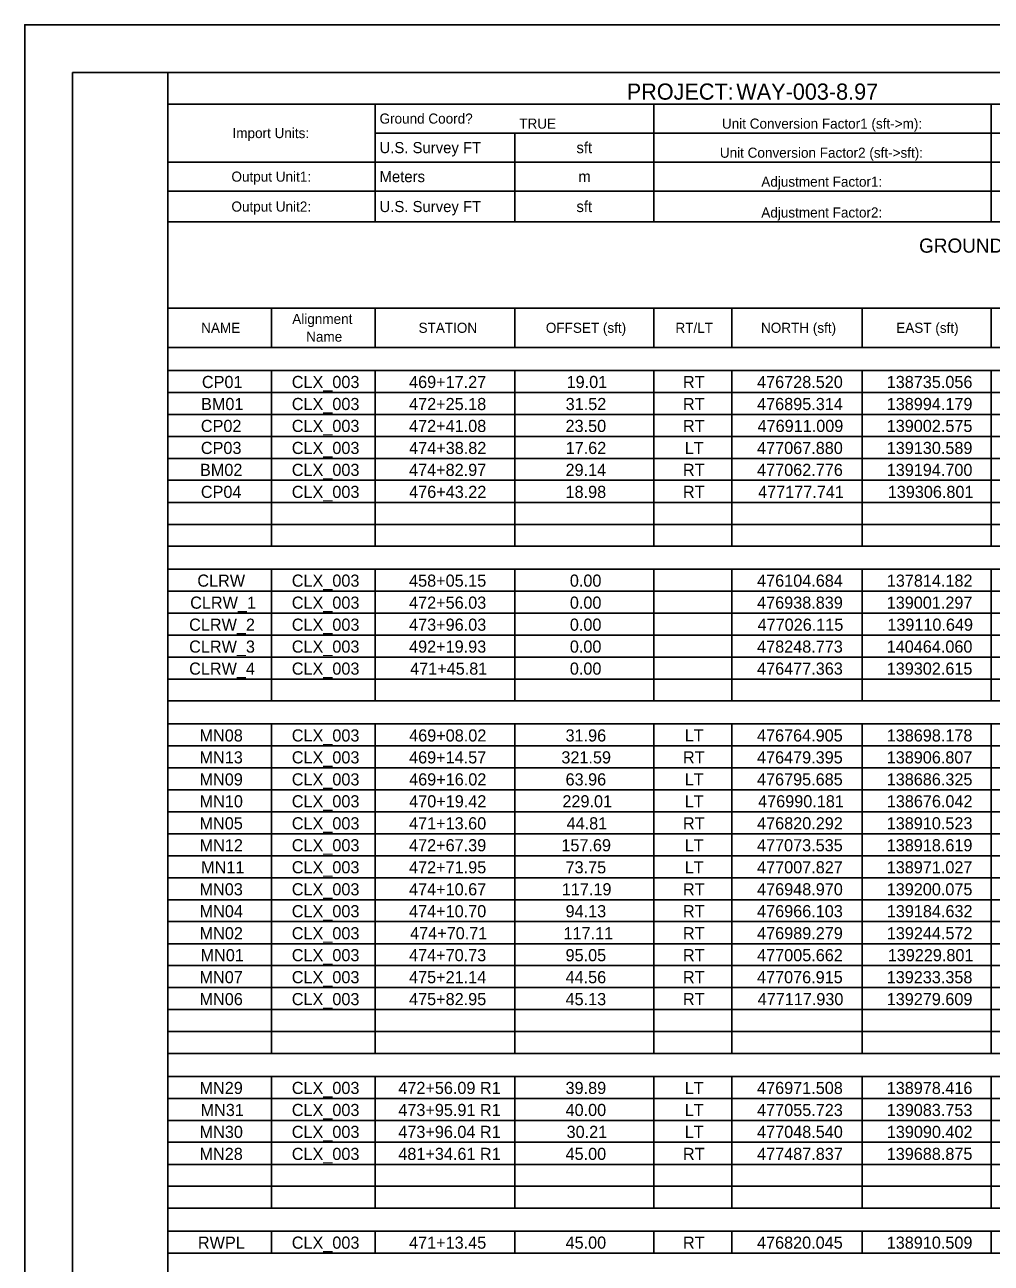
# Model space of a CAD drawing. Extents: x 0 to 34, y 0 to 22.
# Drawn here: x 0 to 10.14, y 9.01 to 22 of the extents above; entities that cross this region are included whole.
import ezdxf

# ---------------------------------------------------------------- set-up
doc = ezdxf.new("R2010")
doc.units = 0
for name, color, linetype in [('SH_Border', 7, 'Continuous'), ('SH_Cut_Line', 7, 'Continuous'), ('SH_Text', 7, 'Continuous')]:
    doc.layers.add(name, color=color, linetype=linetype)

msp = doc.modelspace()

# ---------------------------------------------------------------- linework, layer by layer
at = {"layer": 'SH_Border'}
for points in [[(0.5, 21.5), (1.5, 21.5), (1.5, 0.5), (0.5, 0.5)], [(1.5, 21.5), (33.5, 21.5), (33.5, 0.5), (1.5, 0.5)]]:
    msp.add_lwpolyline(points, close=True, dxfattribs=at)
at = {"layer": 'SH_Cut_Line'}
msp.add_lwpolyline([(0, 0), (34, 0), (34, 22), (0, 22)], close=True, dxfattribs=at)
at = {"layer": 'SH_Text'}
for p, q in [((1.5, 21.168), (10.142, 21.168)), ((1.5, 21.168), (1.5, 19.028)), ((3.677, 21.168), (3.677, 19.932)), ((6.6, 21.168), (6.6, 19.932)), ((10.142, 21.168), (11.59, 21.168)), ((10.142, 21.168), (10.142, 19.932)), ((3.677, 20.864), (10.142, 20.864)), ((5.143, 20.864), (5.143, 19.932)), ((10.142, 20.864), (11.59, 20.864)), ((1.5, 20.559), (6.6, 20.559)), ((6.6, 20.559), (10.142, 20.559)), ((10.142, 20.559), (11.59, 20.559)), ((1.5, 20.255), (10.142, 20.255)), ((10.142, 20.255), (11.59, 20.255)), ((1.5, 19.932), (6.6, 19.932)), ((6.6, 19.932), (10.142, 19.932)), ((10.142, 19.932), (11.59, 19.932)), ((1.5, 19.028), (10.142, 19.028)), ((1.5, 19.028), (1.5, 17.451)), ((2.588, 19.028), (2.588, 18.613)), ((3.677, 19.028), (3.677, 18.613)), ((5.143, 19.028), (5.143, 18.613)), ((6.6, 19.028), (6.6, 18.613)), ((7.421, 19.028), (7.421, 18.613)), ((8.786, 19.028), (8.786, 18.613)), ((10.142, 19.028), (11.59, 19.028)), ((10.142, 19.028), (10.142, 18.613)), ((1.5, 18.613), (10.142, 18.613)), ((10.142, 18.613), (11.59, 18.613)), ((1.5, 18.373), (10.142, 18.373)), ((2.588, 18.373), (2.588, 17.451)), ((3.677, 18.373), (3.677, 17.451)), ((5.143, 18.373), (5.143, 17.451)), ((6.6, 18.373), (6.6, 17.451)), ((7.421, 18.373), (7.421, 17.451)), ((8.786, 18.373), (8.786, 17.451)), ((10.142, 18.373), (11.59, 18.373)), ((10.142, 18.373), (10.142, 17.451)), ((1.5, 18.143), (10.142, 18.143)), ((10.142, 18.143), (11.59, 18.143)), ((1.5, 17.912), (10.142, 17.912)), ((10.142, 17.912), (11.59, 17.912)), ((1.5, 17.682), (10.142, 17.682)), ((10.142, 17.682), (11.59, 17.682)), ((1.5, 17.451), (10.142, 17.451)), ((1.5, 17.451), (1.5, 16.289)), ((2.588, 17.451), (2.588, 16.529)), ((3.677, 17.451), (3.677, 16.529)), ((5.143, 17.451), (5.143, 16.529)), ((6.6, 17.451), (6.6, 16.529)), ((7.421, 17.451), (7.421, 16.529)), ((8.786, 17.451), (8.786, 16.529)), ((10.142, 17.451), (11.59, 17.451)), ((10.142, 17.451), (10.142, 16.529)), ((1.5, 17.221), (10.142, 17.221)), ((10.142, 17.221), (11.59, 17.221)), ((1.5, 16.99), (10.142, 16.99)), ((10.142, 16.99), (11.59, 16.99)), ((1.5, 16.759), (10.142, 16.759)), ((10.142, 16.759), (11.59, 16.759)), ((1.5, 16.529), (10.142, 16.529)), ((10.142, 16.529), (11.59, 16.529)), ((1.5, 16.289), (10.142, 16.289)), ((1.5, 16.289), (1.5, 10.967)), ((2.588, 16.289), (2.588, 14.906)), ((3.677, 16.289), (3.677, 14.906)), ((5.143, 16.289), (5.143, 14.906)), ((6.6, 16.289), (6.6, 14.906)), ((7.421, 16.289), (7.421, 14.906)), ((8.786, 16.289), (8.786, 14.906)), ((10.142, 16.289), (11.59, 16.289)), ((10.142, 16.289), (10.142, 14.906)), ((1.5, 16.059), (10.142, 16.059)), ((10.142, 16.059), (11.59, 16.059)), ((1.5, 15.828), (10.142, 15.828)), ((10.142, 15.828), (11.59, 15.828)), ((1.5, 15.597), (10.142, 15.597)), ((10.142, 15.597), (11.59, 15.597)), ((1.5, 15.367), (10.142, 15.367)), ((10.142, 15.367), (11.59, 15.367)), ((1.5, 15.136), (10.142, 15.136)), ((10.142, 15.136), (11.59, 15.136)), ((1.5, 14.906), (10.142, 14.906)), ((10.142, 14.906), (11.59, 14.906)), ((1.5, 14.666), (10.142, 14.666)), ((2.588, 14.666), (2.588, 11.207)), ((3.677, 14.666), (3.677, 11.207)), ((5.143, 14.666), (5.143, 11.207)), ((6.6, 14.666), (6.6, 11.207)), ((7.421, 14.666), (7.421, 11.207)), ((8.786, 14.666), (8.786, 11.207)), ((10.142, 14.666), (11.59, 14.666)), ((10.142, 14.666), (10.142, 11.207)), ((1.5, 14.435), (10.142, 14.435)), ((10.142, 14.435), (11.59, 14.435)), ((1.5, 14.205), (10.142, 14.205)), ((10.142, 14.205), (11.59, 14.205)), ((1.5, 13.974), (10.142, 13.974)), ((10.142, 13.974), (11.59, 13.974)), ((1.5, 13.744), (10.142, 13.744)), ((10.142, 13.744), (11.59, 13.744)), ((1.5, 13.513), (10.142, 13.513)), ((10.142, 13.513), (11.59, 13.513)), ((1.5, 13.282), (10.142, 13.282)), ((10.142, 13.282), (11.59, 13.282)), ((1.5, 13.052), (10.142, 13.052)), ((10.142, 13.052), (11.59, 13.052)), ((1.5, 12.821), (10.142, 12.821)), ((10.142, 12.821), (11.59, 12.821)), ((1.5, 12.591), (10.142, 12.591)), ((10.142, 12.591), (11.59, 12.591)), ((1.5, 12.36), (10.142, 12.36)), ((10.142, 12.36), (11.59, 12.36)), ((1.5, 12.13), (10.142, 12.13)), ((10.142, 12.13), (11.59, 12.13)), ((1.5, 11.899), (10.142, 11.899)), ((10.142, 11.899), (11.59, 11.899)), ((1.5, 11.668), (10.142, 11.668)), ((10.142, 11.668), (11.59, 11.668)), ((1.5, 11.438), (10.142, 11.438)), ((10.142, 11.438), (11.59, 11.438)), ((1.5, 11.207), (10.142, 11.207)), ((10.142, 11.207), (11.59, 11.207)), ((1.5, 10.967), (10.142, 10.967)), ((1.5, 10.967), (1.5, 9.114)), ((2.588, 10.967), (2.588, 9.584)), ((3.677, 10.967), (3.677, 9.584)), ((5.143, 10.967), (5.143, 9.584)), ((6.6, 10.967), (6.6, 9.584)), ((7.421, 10.967), (7.421, 9.584)), ((8.786, 10.967), (8.786, 9.584)), ((10.142, 10.967), (11.59, 10.967)), ((10.142, 10.967), (10.142, 9.584)), ((1.5, 10.737), (10.142, 10.737)), ((10.142, 10.737), (11.59, 10.737)), ((1.5, 10.506), (10.142, 10.506)), ((10.142, 10.506), (11.59, 10.506)), ((1.5, 10.276), (10.142, 10.276)), ((10.142, 10.276), (11.59, 10.276)), ((1.5, 10.045), (10.142, 10.045)), ((10.142, 10.045), (11.59, 10.045)), ((1.5, 9.815), (10.142, 9.815)), ((10.142, 9.815), (11.59, 9.815)), ((1.5, 9.584), (10.142, 9.584)), ((10.142, 9.584), (11.59, 9.584)), ((1.5, 9.344), (10.142, 9.344)), ((2.588, 9.344), (2.588, 9.114)), ((3.677, 9.344), (3.677, 9.114)), ((5.143, 9.344), (5.143, 9.114)), ((6.6, 9.344), (6.6, 9.114)), ((7.421, 9.344), (7.421, 9.114)), ((8.786, 9.344), (8.786, 9.114)), ((10.142, 9.344), (11.59, 9.344)), ((10.142, 9.344), (10.142, 9.114)), ((1.5, 9.114), (10.142, 9.114)), ((10.142, 9.114), (11.59, 9.114))]:
    msp.add_line(p, q, dxfattribs=at)

# ---------------------------------------------------------------- texts
for s, height, p in [('PROJECT:', 0.1697, (6.317, 21.214)), ('WAY-003-8.97', 0.1697, (7.467, 21.214)), ('Ground Coord?', 0.10606, (3.723, 20.963)), ('Import Units:', 0.10606, (2.18, 20.811)), ('TRUE', 0.1061, (5.189, 20.91)), ('Unit Conversion Factor1 (sft->m):', 0.10606, (7.316, 20.91)), ('U.S. Survey FT', 0.11667, (3.723, 20.653)), ('sft', 0.1167, (5.789, 20.653)), ('Unit Conversion Factor2 (sft->sft):', 0.10606, (7.294, 20.605)), ('Output Unit1:', 0.10606, (2.169, 20.354)), ('Meters', 0.1167, (3.723, 20.349)), ('m', 0.117, (5.809, 20.349)), ('Adjustment Factor1:', 0.10606, (7.729, 20.301)), ('Output Unit2:', 0.10606, (2.169, 20.04)), ('U.S. Survey FT', 0.11667, (3.723, 20.035)), ('sft', 0.1167, (5.789, 20.035)), ('Adjustment Factor2:', 0.10606, (7.729, 19.978)), ('GROUND COORDINATES - U.S. Survey FT', 0.14849, (9.385, 19.609)), ('Alignment ', 0.1061, (2.807, 18.861)), ('NAME', 0.1061, (1.851, 18.768)), ('STATION', 0.1061, (4.132, 18.768)), ('OFFSET (sft)', 0.10606, (5.468, 18.768)), ('RT/LT', 0.1061, (6.828, 18.768)), ('NORTH (sft)', 0.10606, (7.726, 18.768)), ('EAST (sft)', 0.1061, (9.145, 18.768)), ('Name', 0.1061, (2.953, 18.675)), ('CP01', 0.1273, (1.859, 18.189)), ('CLX_003', 0.1273, (2.802, 18.189)), ('469+17.27', 0.1273, (4.033, 18.189)), ('19.01', 0.1273, (5.686, 18.189)), ('RT', 0.1273, (6.907, 18.189)), ('476728.520', 0.1273, (7.685, 18.189)), ('138735.056', 0.1273, (9.045, 18.189)), ('BM01', 0.1273, (1.85, 17.958)), ('CLX_003', 0.1273, (2.802, 17.958)), ('472+25.18', 0.1273, (4.033, 17.958)), ('31.52', 0.1273, (5.676, 17.958)), ('RT', 0.1273, (6.907, 17.958)), ('476895.314', 0.1273, (7.685, 17.958)), ('138994.179', 0.1273, (9.045, 17.958)), ('CP02', 0.1273, (1.848, 17.728)), ('CLX_003', 0.1273, (2.802, 17.728)), ('472+41.08', 0.1273, (4.033, 17.728)), ('23.50', 0.1273, (5.675, 17.728)), ('RT', 0.1273, (6.907, 17.728)), ('476911.009', 0.1273, (7.69, 17.728)), ('139002.575', 0.1273, (9.045, 17.728)), ('CP03', 0.1273, (1.848, 17.497)), ('CLX_003', 0.1273, (2.802, 17.497)), ('474+38.82', 0.1273, (4.034, 17.497)), ('17.62', 0.1273, (5.676, 17.497)), ('LT', 0.1273, (6.925, 17.497)), ('477067.880', 0.1273, (7.685, 17.497)), ('139130.589', 0.1273, (9.045, 17.497)), ('BM02', 0.1273, (1.839, 17.267)), ('CLX_003', 0.1273, (2.802, 17.267)), ('474+82.97', 0.1273, (4.033, 17.267)), ('29.14', 0.1273, (5.675, 17.267)), ('RT', 0.1273, (6.907, 17.267)), ('477062.776', 0.1273, (7.685, 17.267)), ('139194.700', 0.1273, (9.045, 17.267)), ('CP04', 0.1273, (1.848, 17.036)), ('CLX_003', 0.1273, (2.802, 17.036)), ('476+43.22', 0.1273, (4.034, 17.036)), ('18.98', 0.1273, (5.675, 17.036)), ('RT', 0.1273, (6.907, 17.036)), ('477177.741', 0.1273, (7.696, 17.036)), ('139306.801', 0.1273, (9.056, 17.036)), ('CLRW', 0.1273, (1.811, 16.105)), ('CLX_003', 0.1273, (2.802, 16.105)), ('458+05.15', 0.1273, (4.033, 16.105)), ('0.00', 0.1273, (5.72, 16.105)), ('476104.684', 0.1273, (7.685, 16.105)), ('137814.182', 0.1273, (9.046, 16.105)), ('CLRW_1', 0.1273, (1.736, 15.874)), ('CLX_003', 0.1273, (2.802, 15.874)), ('472+56.03', 0.1273, (4.033, 15.874)), ('0.00', 0.1273, (5.72, 15.874)), ('476938.839', 0.1273, (7.685, 15.874)), ('139001.297', 0.1273, (9.045, 15.874)), ('CLRW_2', 0.1273, (1.725, 15.643)), ('CLX_003', 0.1273, (2.802, 15.643)), ('473+96.03', 0.1273, (4.033, 15.643)), ('0.00', 0.1273, (5.72, 15.643)), ('477026.115', 0.1273, (7.69, 15.643)), ('139110.649', 0.1273, (9.051, 15.643)), ('CLRW_3', 0.1273, (1.725, 15.413)), ('CLX_003', 0.1273, (2.802, 15.413)), ('492+19.93', 0.1273, (4.033, 15.413)), ('0.00', 0.1273, (5.72, 15.413)), ('478248.773', 0.1273, (7.685, 15.413)), ('140464.060', 0.1273, (9.045, 15.413)), ('CLRW_4', 0.1273, (1.725, 15.182)), ('CLX_003', 0.1273, (2.802, 15.182)), ('471+45.81', 0.1273, (4.044, 15.182)), ('0.00', 0.1273, (5.72, 15.182)), ('476477.363', 0.1273, (7.685, 15.182)), ('139302.615', 0.1273, (9.045, 15.182)), ('MN08', 0.1273, (1.834, 14.481)), ('CLX_003', 0.1273, (2.802, 14.481)), ('469+08.02', 0.1273, (4.034, 14.481)), ('31.96', 0.1273, (5.675, 14.481)), ('LT', 0.1273, (6.925, 14.481)), ('476764.905', 0.1273, (7.684, 14.481)), ('138698.178', 0.1273, (9.045, 14.481)), ('MN13', 0.1273, (1.834, 14.251)), ('CLX_003', 0.1273, (2.802, 14.251)), ('469+14.57', 0.1273, (4.033, 14.251)), ('321.59', 0.1273, (5.631, 14.251)), ('RT', 0.1273, (6.907, 14.251)), ('476479.395', 0.1273, (7.684, 14.251)), ('138906.807', 0.1273, (9.045, 14.251)), ('MN09', 0.1273, (1.834, 14.02)), ('CLX_003', 0.1273, (2.802, 14.02)), ('469+16.02', 0.1273, (4.034, 14.02)), ('63.96', 0.1273, (5.675, 14.02)), ('LT', 0.1273, (6.925, 14.02)), ('476795.685', 0.1273, (7.684, 14.02)), ('138686.325', 0.1273, (9.045, 14.02)), ('MN10', 0.1273, (1.835, 13.79)), ('CLX_003', 0.1273, (2.802, 13.79)), ('470+19.42', 0.1273, (4.034, 13.79)), ('229.01', 0.1273, (5.642, 13.79)), ('LT', 0.1273, (6.925, 13.79)), ('476990.181', 0.1273, (7.696, 13.79)), ('138676.042', 0.1273, (9.046, 13.79)), ('MN05', 0.1273, (1.834, 13.559)), ('CLX_003', 0.1273, (2.802, 13.559)), ('471+13.60', 0.1273, (4.033, 13.559)), ('44.81', 0.1273, (5.686, 13.559)), ('RT', 0.1273, (6.907, 13.559)), ('476820.292', 0.1273, (7.685, 13.559)), ('138910.523', 0.1273, (9.045, 13.559)), ('MN12', 0.1273, (1.835, 13.329)), ('CLX_003', 0.1273, (2.802, 13.329)), ('472+67.39', 0.1273, (4.033, 13.329)), ('157.69', 0.1273, (5.631, 13.329)), ('LT', 0.1273, (6.925, 13.329)), ('477073.535', 0.1273, (7.684, 13.329)), ('138918.619', 0.1273, (9.045, 13.329)), ('MN11', 0.1273, (1.851, 13.098)), ('CLX_003', 0.1273, (2.802, 13.098)), ('472+71.95', 0.1273, (4.033, 13.098)), ('73.75', 0.1273, (5.675, 13.098)), ('LT', 0.1273, (6.925, 13.098)), ('477007.827', 0.1273, (7.685, 13.098)), ('138971.027', 0.1273, (9.045, 13.098)), ('MN03', 0.1273, (1.834, 12.867)), ('CLX_003', 0.1273, (2.802, 12.867)), ('474+10.67', 0.1273, (4.033, 12.867)), ('117.19', 0.1273, (5.636, 12.867)), ('RT', 0.1273, (6.907, 12.867)), ('476948.970', 0.1273, (7.685, 12.867)), ('139200.075', 0.1273, (9.045, 12.867)), ('MN04', 0.1273, (1.835, 12.637)), ('CLX_003', 0.1273, (2.802, 12.637)), ('474+10.70', 0.1273, (4.033, 12.637)), ('94.13', 0.1273, (5.675, 12.637)), ('RT', 0.1273, (6.907, 12.637)), ('476966.103', 0.1273, (7.685, 12.637)), ('139184.632', 0.1273, (9.046, 12.637)), ('MN02', 0.1273, (1.835, 12.406)), ('CLX_003', 0.1273, (2.802, 12.406)), ('474+70.71', 0.1273, (4.044, 12.406)), ('117.11', 0.1273, (5.654, 12.406)), ('RT', 0.1273, (6.907, 12.406)), ('476989.279', 0.1273, (7.685, 12.406)), ('139244.572', 0.1273, (9.046, 12.406)), ('MN01', 0.1273, (1.845, 12.176)), ('CLX_003', 0.1273, (2.802, 12.176)), ('474+70.73', 0.1273, (4.033, 12.176)), ('95.05', 0.1273, (5.675, 12.176)), ('RT', 0.1273, (6.907, 12.176)), ('477005.662', 0.1273, (7.685, 12.176)), ('139229.801', 0.1273, (9.056, 12.176)), ('MN07', 0.1273, (1.834, 11.945)), ('CLX_003', 0.1273, (2.802, 11.945)), ('475+21.14', 0.1273, (4.033, 11.945)), ('44.56', 0.1273, (5.675, 11.945)), ('RT', 0.1273, (6.907, 11.945)), ('477076.915', 0.1273, (7.684, 11.945)), ('139233.358', 0.1273, (9.045, 11.945)), ('MN06', 0.1273, (1.834, 11.715)), ('CLX_003', 0.1273, (2.802, 11.715)), ('475+82.95', 0.1273, (4.033, 11.715)), ('45.13', 0.1273, (5.675, 11.715)), ('RT', 0.1273, (6.907, 11.715)), ('477117.930', 0.1273, (7.691, 11.715)), ('139279.609', 0.1273, (9.045, 11.715)), ('MN29', 0.1273, (1.834, 10.783)), ('CLX_003', 0.1273, (2.802, 10.783)), ('472+56.09 R1', 0.12728, (3.92, 10.783)), ('39.89', 0.1273, (5.675, 10.783)), ('LT', 0.1273, (6.925, 10.783)), ('476971.508', 0.1273, (7.685, 10.783)), ('138978.416', 0.1273, (9.045, 10.783)), ('MN31', 0.1273, (1.845, 10.552)), ('CLX_003', 0.1273, (2.802, 10.552)), ('473+95.91 R1', 0.12728, (3.92, 10.552)), ('40.00', 0.1273, (5.675, 10.552)), ('LT', 0.1273, (6.925, 10.552)), ('477055.723', 0.1273, (7.685, 10.552)), ('139083.753', 0.1273, (9.045, 10.552)), ('MN30', 0.1273, (1.835, 10.322)), ('CLX_003', 0.1273, (2.802, 10.322)), ('473+96.04 R1', 0.12728, (3.92, 10.322)), ('30.21', 0.1273, (5.686, 10.322)), ('LT', 0.1273, (6.925, 10.322)), ('477048.540', 0.1273, (7.685, 10.322)), ('139090.402', 0.1273, (9.046, 10.322)), ('MN28', 0.1273, (1.834, 10.091)), ('CLX_003', 0.1273, (2.802, 10.091)), ('481+34.61 R1', 0.12728, (3.92, 10.091)), ('45.00', 0.1273, (5.675, 10.091)), ('RT', 0.1273, (6.907, 10.091)), ('477487.837', 0.1273, (7.685, 10.091)), ('139688.875', 0.1273, (9.045, 10.091)), ('RWPL', 0.1273, (1.817, 9.16)), ('CLX_003', 0.1273, (2.802, 9.16)), ('471+13.45', 0.1273, (4.033, 9.16)), ('45.00', 0.1273, (5.675, 9.16)), ('RT', 0.1273, (6.907, 9.16)), ('476820.045', 0.1273, (7.684, 9.16)), ('138910.509', 0.1273, (9.045, 9.16))]:
    msp.add_text(s, height=height, dxfattribs=at).set_placement(p)

doc.saveas('drawing.dxf')
